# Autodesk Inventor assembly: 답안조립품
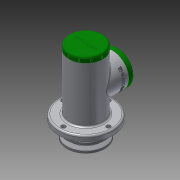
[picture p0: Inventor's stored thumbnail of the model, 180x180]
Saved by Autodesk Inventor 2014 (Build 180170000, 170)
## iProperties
Created: 2016-08
Part Number: 답안조립품
Document SubType Name: Assembly
Designer: user
Author: user
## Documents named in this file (24)
- C:\Users\user\Desktop\답안조립품.iam
- C:\Users\user\Desktop\답안도면.ipt
- C:\Users\user\Desktop\460808v1005\편심축.ipt
- C:\Users\user\Desktop\460808v1005\링크.ipt
- C:\Users\user\Desktop\460808v1005\부시1.ipt
- C:\Users\user\Desktop\460808v1005\베어링 15 x 35 x 11.ipt
- C:\Users\user\Desktop\460808v1005\멈춤링 15 x 1.ipt
- C:\Users\user\Desktop\460808v1005\멈춤링 35x1.6.ipt
- C:\Users\user\Desktop\460808v1005\부시2.ipt
- C:\Users\user\Desktop\460808v1005\오일 실 15 25 7.ipt
- C:\Users\user\Desktop\460808v1005\키 4 x 4 x 18.ipt
- C:\Users\user\Desktop\460808v1005\V-벨트풀리.ipt
- C:\Users\user\Desktop\460808v1005\와셔 4x16.ipt
- C:\Users\user\Desktop\460808v1005\볼트 M4 x 10.ipt
- C:\Users\user\Desktop\460808v1005\와셔 10x21.ipt
- C:\Users\user\Desktop\460808v1005\너트 M10.ipt
- C:\Users\user\Desktop\460808v1005\슬라이더.ipt
- C:\Users\user\Desktop\460808v1005\클래스터 핀 6 x 24.ipt
- C:\Users\user\Desktop\460808v1005\사이드 커버.ipt
- 사이드 커버.ipt
- C:\Users\user\Desktop\460808v1005\탑 커버.ipt
- 탑 커버.ipt
- C:\Users\user\Desktop\460808v1005\볼트 M4 x 12.ipt
- C:\Users\user\Desktop\460808v1005\탑 부시.ipt
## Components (6 placed, 3 different names)
1. V-벨트풀리:1 — Mate:21, Mate:22, Mate:23
2. ISO 4017 M4 x 10:1 — Mate:26, Mate:27
3. ISO 4762 M4 x 12:1 — Mate:44, Mate:45
4. ISO 4762 M4 x 12:2
5. ISO 4762 M4 x 12:3
6. ISO 4762 M4 x 12:4
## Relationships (7: Mate 7)
- Mate:21: V-벨트풀리:1
- Mate:22: V-벨트풀리:1
- Mate:23: V-벨트풀리:1
- Mate:26: ISO 4017 M4 x 10:1
- Mate:27: ISO 4017 M4 x 10:1
- Mate:44: ISO 4762 M4 x 12:1
- Mate:45: ISO 4762 M4 x 12:1
